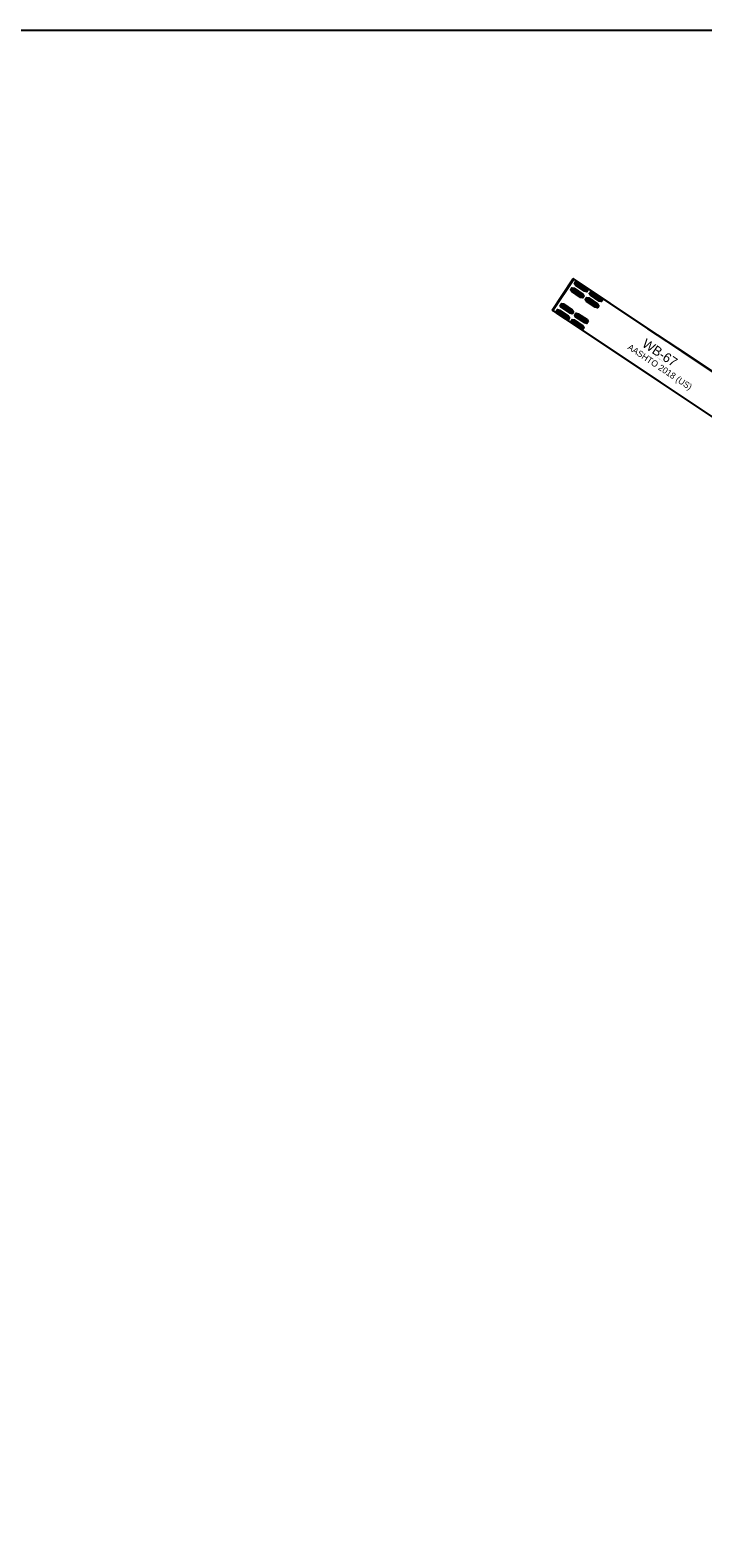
# Model space of a CAD drawing. Extents: x 973688 to 979179, y 703586 to 707602.
# Drawn here: x 978212.4 to 978364.3, y 703808.9 to 704149.2 of the extents above; entities that cross this region are included whole.
import ezdxf

# ---------------------------------------------------------------- set-up
doc = ezdxf.new("R2010")
doc.units = 0
doc.layers.add('NO PLOT', color=7, linetype='Continuous')
doc.layers.add('T_Drafting', color=7, linetype='Continuous')

msp = doc.modelspace()

# ---------------------------------------------------------------- linework, layer by layer
at = {"layer": 'NO PLOT'}
msp.add_lwpolyline([(978152.67, 704149.22), (978832.67, 704149.22), (978832.67, 703709.22), (978152.67, 703709.22)], close=True, dxfattribs=at)
at = {"layer": 'T_Drafting'}
for p, q in [((978330.48, 704085.94), (978335.19, 704093.01)), ((978332.78, 704089.52), (978332.84, 704089.48)), ((978332.92, 704089.74), (978333.07, 704089.96)), ((978337.23, 704088.85), (978334.49, 704090.68)), ((978337.36, 704089.04), (978334.61, 704090.87)), ((978337.49, 704089.23), (978334.74, 704091.06)), ((978338.15, 704090.22), (978335.4, 704092.05)), ((978338.27, 704090.41), (978335.53, 704092.24)), ((978338.4, 704090.6), (978335.66, 704092.43)), ((978341.47, 704088), (978338.73, 704089.83)), ((978341.6, 704088.19), (978338.86, 704090.02)), ((978341.73, 704088.38), (978338.98, 704090.21)), ((978334.19, 704084.29), (978331.45, 704086.12)), ((978334.85, 704085.28), (978332.11, 704087.11)), ((978334.98, 704085.47), (978332.24, 704087.3)), ((978335.11, 704085.66), (978332.36, 704087.49)), ((978332.48, 704089.08), (978332.63, 704089.3)), ((978340.56, 704086.63), (978337.81, 704088.46)), ((978340.69, 704086.82), (978337.94, 704088.65)), ((978340.81, 704087.01), (978338.07, 704088.84)), ((978333.94, 704083.91), (978331.19, 704085.74)), ((978334.07, 704084.1), (978331.32, 704085.93)), ((978337.27, 704081.69), (978334.52, 704083.52)), ((978337.39, 704081.88), (978334.65, 704083.71)), ((978337.52, 704082.07), (978334.78, 704083.9)), ((978338.18, 704083.06), (978335.44, 704084.89)), ((978338.31, 704083.25), (978335.56, 704085.08)), ((978338.44, 704083.44), (978335.69, 704085.27))]:
    msp.add_line(p, q, dxfattribs=at)
for points in [[(978380.8, 704052.39), (978330.36, 704086.02), (978335.08, 704093.09), (978335.21, 704093), (978335.21, 704093)], [(978330.43, 704086), (978330.42, 704085.98), (978330.48, 704085.94), (978335.19, 704082.8), (978374.45, 704056.61), (978376.81, 704060.15), (978379.17, 704063.68), (978339.91, 704089.87), (978335.19, 704093.01), (978335.13, 704093.05), (978335.12, 704093.03)], [(978335.11, 704093.01), (978335.11, 704093.01), (978333.09, 704089.99), (978333.07, 704089.96), (978333.01, 704090), (978333.01, 704090), (978332.86, 704089.78)], [(978335.21, 704093), (978351.87, 704081.9), (978360.76, 704075.99), (978369.66, 704070.1)], [(978332.92, 704089.73), (978332.63, 704089.3)], [(978332.57, 704089.34), (978332.42, 704089.12), (978332.42, 704089.11), (978332.48, 704089.08), (978332.46, 704089.05), (978330.44, 704086.02), (978330.44, 704086.02)]]:
    msp.add_lwpolyline(points, dxfattribs=at)
for points in [[(978337.52, 704089.27), (978337.2, 704088.8), (978336.72, 704088.91), (978334.74, 704090.23), (978334.45, 704090.63), (978334.77, 704091.1), (978335.25, 704090.99), (978337.23, 704089.67)], [(978338.43, 704090.65), (978338.12, 704090.17), (978337.64, 704090.28), (978335.66, 704091.6), (978335.37, 704092), (978335.69, 704092.48), (978336.17, 704092.36), (978338.14, 704091.05)], [(978341.76, 704088.43), (978341.44, 704087.95), (978340.96, 704088.06), (978338.99, 704089.38), (978338.7, 704089.78), (978339.02, 704090.26), (978339.5, 704090.14), (978341.47, 704088.83)], [(978334.23, 704084.34), (978333.91, 704083.86), (978333.43, 704083.97), (978331.45, 704085.29), (978331.16, 704085.69), (978331.48, 704086.17), (978331.96, 704086.06), (978333.94, 704084.74)], [(978335.14, 704085.71), (978334.82, 704085.23), (978334.34, 704085.35), (978332.37, 704086.67), (978332.08, 704087.07), (978332.4, 704087.54), (978332.88, 704087.43), (978334.85, 704086.11)], [(978340.85, 704087.05), (978340.53, 704086.58), (978340.05, 704086.69), (978338.07, 704088.01), (978337.78, 704088.41), (978338.1, 704088.89), (978338.58, 704088.77), (978340.56, 704087.45)], [(978337.55, 704082.12), (978337.24, 704081.64), (978336.76, 704081.76), (978334.78, 704083.07), (978334.49, 704083.47), (978334.81, 704083.95), (978335.29, 704083.84), (978337.26, 704082.52)], [(978338.47, 704083.49), (978338.15, 704083.01), (978337.67, 704083.13), (978335.69, 704084.45), (978335.41, 704084.85), (978335.72, 704085.32), (978336.2, 704085.21), (978338.18, 704083.89)]]:
    msp.add_lwpolyline(points, close=True, dxfattribs=at)
for centre in [(978335.09, 704093.04), (978330.41, 704086.03)]:
    msp.add_circle(centre, 0.0266, dxfattribs=at)
for centre, radius, start, end in [((978335.09, 704093.04), 0.0363, 345.3718, 306.5331), ((978332.89, 704089.76), 0.0353, 329.6305, 147.9801), ((978332.89, 704089.76), 0.0352, 146.3196, 325.32), ((978332.6, 704089.32), 0.0352, 327.2686, 146.269), ((978332.6, 704089.32), 0.0354, 150.5858, 322.7713), ((978328.75, 704087.12), 2.02, 326.2943, 326.9781)]:
    msp.add_arc(centre, radius, start, end, dxfattribs=at)

# ---------------------------------------------------------------- texts
for s, height, p in [('WB-67', 2.125, (978350.44, 704077.94)), ('AASHTO 2018 (US)', 1.4167, (978347.2, 704077.33)), ('(c) 2021 Transoft Solutions, Inc. All rights reserved.', 0.085, (978353.3, 704075.78))]:
    msp.add_text(s, height=height, rotation=326.2943, dxfattribs=at).set_placement(p)

doc.saveas('drawing.dxf')
